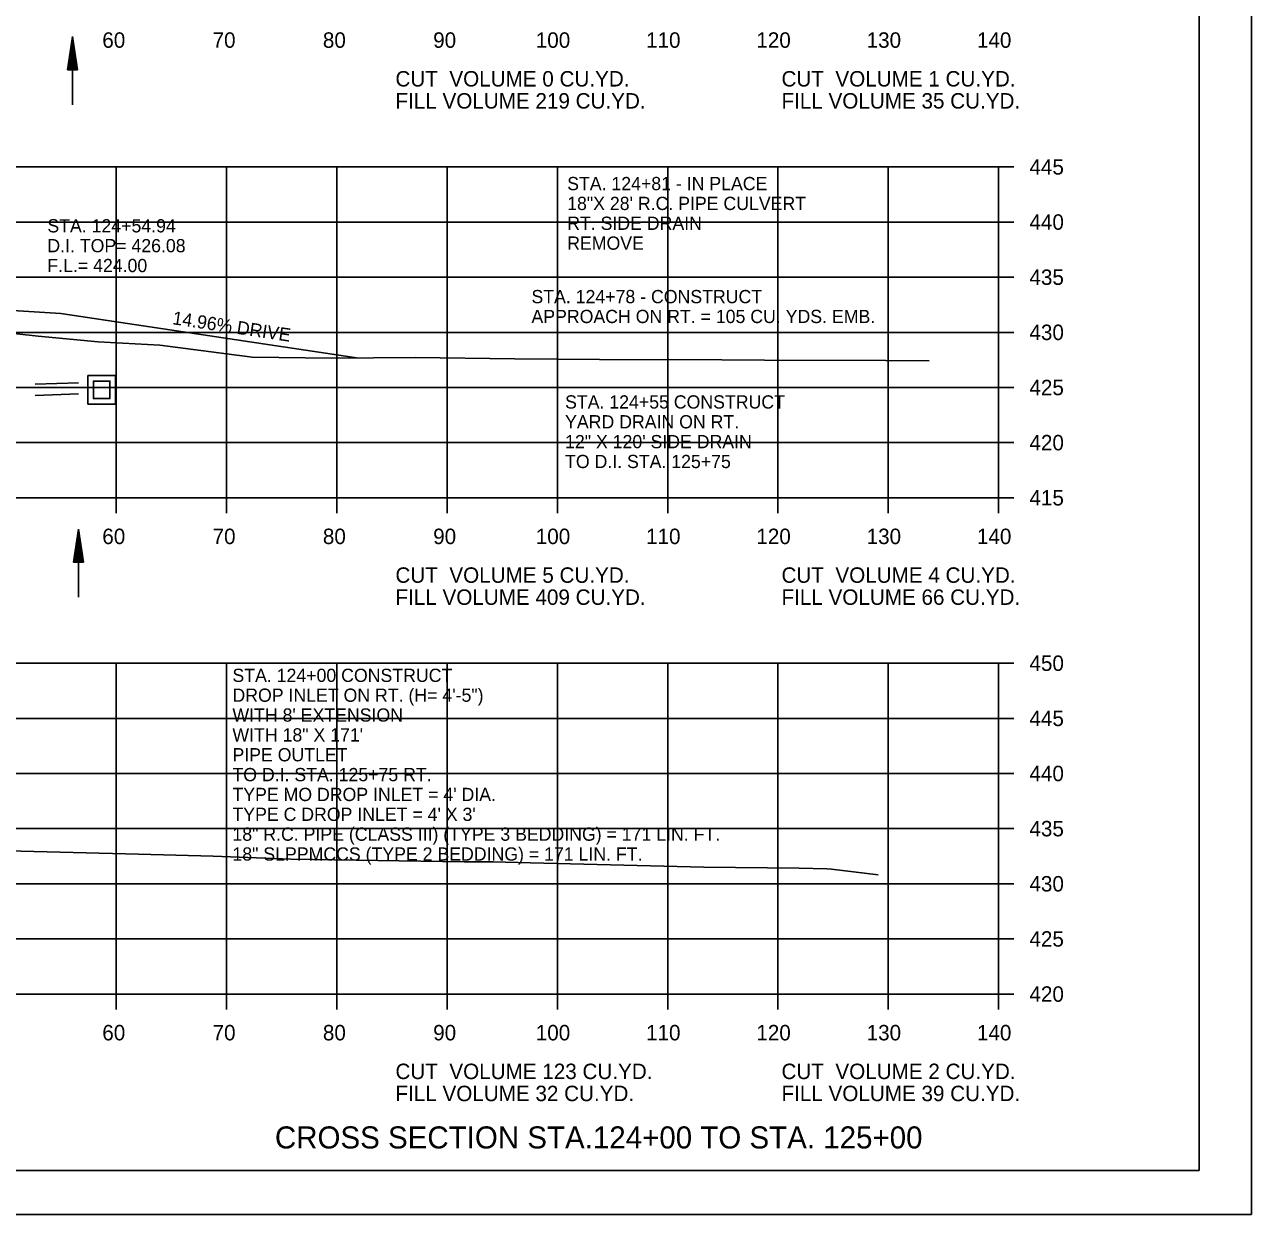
# Model space of a CAD drawing. Extents: x 1538688 to 1540766, y 656250 to 671912.
# Drawn here: x 1538909.9 to 1539021.1, y 659751.3 to 659859.2 of the extents above; entities that cross this region are included whole.
import ezdxf

# ---------------------------------------------------------------- set-up
doc = ezdxf.new("R2010")
doc.units = 0
for name, color, linetype in [('15', 7, 'Continuous'), ('16', 7, 'Continuous'), ('18', 7, 'Continuous'), ('22', 7, 'Continuous'), ('26', 7, 'Continuous'), ('39', 7, 'Continuous'), ('40', 7, 'Continuous'), ('7', 7, 'Continuous'), ('Borings', 7, 'Continuous'), ('Default', 7, 'Continuous'), ('Horizontal Alignment', 7, 'Continuous'), ('RipRap', 7, 'Continuous')]:
    doc.layers.add(name, color=color, linetype=linetype)

msp = doc.modelspace()

# ---------------------------------------------------------------- linework, layer by layer
at = {"layer": '15'}
for p, q in [((1538913.78, 659855.1), (1538914.23, 659858.1)), ((1538914.68, 659855.1), (1538914.23, 659858.1)), ((1538913.86, 659855.1), (1538914.23, 659857.6)), ((1538913.94, 659855.1), (1538914.23, 659857.09)), ((1538914.61, 659855.1), (1538914.23, 659857.6)), ((1538914.53, 659855.1), (1538914.23, 659857.09)), ((1538914.01, 659855.1), (1538914.23, 659856.59)), ((1538914.09, 659855.1), (1538914.23, 659856.08)), ((1538914.46, 659855.1), (1538914.23, 659856.59)), ((1538914.38, 659855.1), (1538914.23, 659856.08)), ((1538913.78, 659855.1), (1538914.68, 659855.1)), ((1538914.16, 659855.1), (1538914.23, 659855.58)), ((1538914.3, 659855.1), (1538914.23, 659855.58)), ((1538914.32, 659810.45), (1538914.77, 659813.45)), ((1538914.39, 659810.45), (1538914.77, 659812.95)), ((1538914.47, 659810.45), (1538914.77, 659812.44)), ((1538915.22, 659810.45), (1538914.77, 659813.45)), ((1538915.14, 659810.45), (1538914.77, 659812.95)), ((1538915.07, 659810.45), (1538914.77, 659812.44)), ((1538914.54, 659810.45), (1538914.77, 659811.94)), ((1538914.62, 659810.45), (1538914.77, 659811.43)), ((1538914.99, 659810.45), (1538914.77, 659811.94)), ((1538914.92, 659810.45), (1538914.77, 659811.43)), ((1538914.32, 659810.45), (1538915.22, 659810.45)), ((1538914.7, 659810.45), (1538914.77, 659810.93)), ((1538914.84, 659810.45), (1538914.77, 659810.93))]:
    msp.add_line(p, q, dxfattribs=at)
at = {"layer": '16'}
for p, q in [((1538913.16, 659833.01), (1538903.17, 659833.6)), ((1538940.18, 659828.96), (1538913.16, 659833.01))]:
    msp.add_line(p, q, dxfattribs=at)
at = {"layer": '18'}
for points in [[(1538897.8, 659832.4), (1538911.1, 659830.95), (1538916.56, 659830.42), (1538922.14, 659830.13), (1538930.52, 659829.04), (1538937.72, 659828.95), (1538945.3, 659829), (1538954.31, 659828.89), (1538958.18, 659828.87), (1538962.01, 659828.84), (1538973.08, 659828.8), (1538976.97, 659828.78), (1538987.95, 659828.74), (1538991.9, 659828.72)], [(1538908.35, 659784.29), (1538920.2, 659783.96), (1538926.98, 659783.8), (1538934.03, 659783.53), (1538949.74, 659783.29), (1538952.36, 659783.27), (1538955.73, 659783.2), (1538971.47, 659782.8), (1538980.1, 659782.69), (1538982.6, 659782.65), (1538983.03, 659782.6), (1538987.28, 659782.1)]]:
    msp.add_lwpolyline(points, dxfattribs=at)
at = {"layer": '22'}
for p, q in [((1538718.18, 659846.29), (1538998.18, 659846.29)), ((1538918.18, 659816.29), (1538918.18, 659846.29)), ((1538928.18, 659816.29), (1538928.18, 659846.29)), ((1538938.18, 659816.29), (1538938.18, 659846.29)), ((1538948.18, 659816.29), (1538948.18, 659846.29)), ((1538958.18, 659816.29), (1538958.18, 659846.29)), ((1538968.18, 659816.29), (1538968.18, 659846.29)), ((1538978.18, 659816.29), (1538978.18, 659846.29)), ((1538988.18, 659816.29), (1538988.18, 659846.29)), ((1538998.18, 659816.29), (1538998.18, 659846.29)), ((1538718.18, 659841.29), (1538998.18, 659841.29)), ((1538718.18, 659836.29), (1538998.18, 659836.29)), ((1538718.18, 659831.29), (1538998.18, 659831.29)), ((1538718.18, 659826.29), (1538998.18, 659826.29)), ((1538718.18, 659821.29), (1538998.18, 659821.29)), ((1538718.18, 659816.29), (1538998.18, 659816.29)), ((1538718.18, 659801.29), (1538998.18, 659801.29)), ((1538918.18, 659771.29), (1538918.18, 659801.29)), ((1538928.18, 659771.29), (1538928.18, 659801.29)), ((1538938.18, 659771.29), (1538938.18, 659801.29)), ((1538948.18, 659771.29), (1538948.18, 659801.29)), ((1538958.18, 659771.29), (1538958.18, 659801.29)), ((1538968.18, 659771.29), (1538968.18, 659801.29)), ((1538978.18, 659771.29), (1538978.18, 659801.29)), ((1538988.18, 659771.29), (1538988.18, 659801.29)), ((1538998.18, 659771.29), (1538998.18, 659801.29)), ((1538718.18, 659796.29), (1538998.18, 659796.29)), ((1538718.18, 659791.29), (1538998.18, 659791.29)), ((1538718.18, 659786.29), (1538998.18, 659786.29)), ((1538718.18, 659781.29), (1538998.18, 659781.29)), ((1538718.18, 659776.29), (1538998.18, 659776.29)), ((1538718.18, 659771.29), (1538998.18, 659771.29))]:
    msp.add_line(p, q, dxfattribs=at)
at = {"layer": '26'}
for p, q in [((1538914.76, 659826.72), (1538910.82, 659826.58)), ((1538914.76, 659825.71), (1538910.82, 659825.57)), ((1538687.78, 659751.31), (1539021.11, 659751.31))]:
    msp.add_line(p, q, dxfattribs=at)
msp.add_lwpolyline([(1538687.77, 659964.64), (1539021.11, 659964.64), (1539021.11, 659751.31), (1538687.77, 659751.31)], close=True, dxfattribs=at)
at = {"layer": '39'}
for p, q in [((1538914.23, 659851.92), (1538914.23, 659858.1)), ((1538914.77, 659807.27), (1538914.77, 659813.45))]:
    msp.add_line(p, q, dxfattribs=at)
for points in [[(1538916.86, 659827.37), (1538918.11, 659827.37), (1538918.11, 659824.79), (1538916.86, 659824.79), (1538915.61, 659824.79), (1538915.61, 659827.37)], [(1538916.86, 659826.87), (1538917.61, 659826.87), (1538917.61, 659825.29), (1538916.86, 659825.29), (1538916.11, 659825.29), (1538916.11, 659826.87)]]:
    msp.add_lwpolyline(points, close=True, dxfattribs=at)
at = {"layer": 'Borings'}
for p, q in [((1538998.18, 659816.29), (1538998.18, 659846.29)), ((1538999.58, 659846.29), (1538998.18, 659846.29)), ((1538999.58, 659841.29), (1538998.18, 659841.29)), ((1538999.58, 659836.29), (1538998.18, 659836.29)), ((1538999.58, 659831.29), (1538998.18, 659831.29)), ((1538999.58, 659826.29), (1538998.18, 659826.29)), ((1538999.58, 659821.29), (1538998.18, 659821.29)), ((1538718.18, 659816.29), (1538998.18, 659816.29)), ((1538918.18, 659814.89), (1538918.18, 659816.29)), ((1538928.18, 659814.89), (1538928.18, 659816.29)), ((1538938.18, 659814.89), (1538938.18, 659816.29)), ((1538948.18, 659814.89), (1538948.18, 659816.29)), ((1538958.18, 659814.89), (1538958.18, 659816.29)), ((1538968.18, 659814.89), (1538968.18, 659816.29)), ((1538978.18, 659814.89), (1538978.18, 659816.29)), ((1538988.18, 659814.89), (1538988.18, 659816.29)), ((1538998.18, 659814.89), (1538998.18, 659816.29)), ((1538999.58, 659816.29), (1538998.18, 659816.29)), ((1538998.18, 659771.29), (1538998.18, 659801.29)), ((1538999.58, 659801.29), (1538998.18, 659801.29)), ((1538999.58, 659796.29), (1538998.18, 659796.29)), ((1538999.58, 659791.29), (1538998.18, 659791.29)), ((1538999.58, 659786.29), (1538998.18, 659786.29)), ((1538999.58, 659781.29), (1538998.18, 659781.29)), ((1538999.58, 659776.29), (1538998.18, 659776.29)), ((1538718.18, 659771.29), (1538998.18, 659771.29)), ((1538918.18, 659769.89), (1538918.18, 659771.29)), ((1538928.18, 659769.89), (1538928.18, 659771.29)), ((1538938.18, 659769.89), (1538938.18, 659771.29)), ((1538948.18, 659769.89), (1538948.18, 659771.29)), ((1538958.18, 659769.89), (1538958.18, 659771.29)), ((1538968.18, 659769.89), (1538968.18, 659771.29)), ((1538978.18, 659769.89), (1538978.18, 659771.29)), ((1538988.18, 659769.89), (1538988.18, 659771.29)), ((1538998.18, 659769.89), (1538998.18, 659771.29)), ((1538999.58, 659771.29), (1538998.18, 659771.29))]:
    msp.add_line(p, q, dxfattribs=at)
at = {"layer": 'RipRap'}
for q in [(1539016.36, 659960.75), (1538700.18, 659755.29)]:
    msp.add_line((1539016.36, 659755.29), q, dxfattribs=at)

# ---------------------------------------------------------------- texts
at = {"layer": '15'}
msp.add_text('CROSS SECTION STA.124+00 TO STA. 125+00', height=2, dxfattribs=at).set_placement((1538932.57, 659757.29))
at = {"layer": '16'}
msp.add_text('14.96% DRIVE', height=1.2, rotation=351.4914, dxfattribs=at).set_placement((1538923.23, 659832.03))
at = {"layer": '40'}
for s, p in [('STA. 124+54.94', (1538911.94, 659840.35)), ('D.I. TOP= 426.08', (1538911.94, 659838.55)), ('F.L.= 424.00', (1538911.94, 659836.75)), ('STA. 124+55 CONSTRUCT', (1538958.88, 659824.38)), ('YARD DRAIN ON RT. ', (1538958.88, 659822.58)), ('12" X 120\' SIDE DRAIN', (1538958.88, 659820.78)), ('TO D.I. STA. 125+75', (1538958.88, 659818.98)), ('STA. 124+00 CONSTRUCT', (1538928.72, 659799.59)), ('DROP INLET ON RT. (H= 4\'-5") ', (1538928.72, 659797.79)), ("WITH 8' EXTENSION ", (1538928.72, 659795.99)), ('WITH 18" X 171\'', (1538928.72, 659794.19)), ('PIPE OUTLET', (1538928.72, 659792.39)), ('TO D.I. STA. 125+75 RT.', (1538928.72, 659790.59)), ("TYPE MO DROP INLET = 4' DIA.", (1538928.72, 659788.79)), ("TYPE C DROP INLET = 4' X 3'", (1538928.72, 659786.99)), ('18" R.C. PIPE (CLASS III) (TYPE 3 BEDDING) = 171 LIN. FT.', (1538928.72, 659785.19)), ('18" SLPPMCCS (TYPE 2 BEDDING) = 171 LIN. FT.', (1538928.72, 659783.39))]:
    msp.add_text(s, height=1.2, dxfattribs=at).set_placement(p)
at = {"layer": '7'}
for s, p in [('STA. 124+78 - CONSTRUCT', (1538955.83, 659833.93)), ('APPROACH ON RT. = 105 CU. YDS. EMB.', (1538955.83, 659832.13))]:
    msp.add_text(s, height=1.2, dxfattribs=at).set_placement(p)
at = {"layer": 'Default'}
for s, p in [('STA. 124+81 - IN PLACE', (1538959.07, 659844.18)), ('18"X 28\' R.C. PIPE CULVERT', (1538959.07, 659842.38)), ('RT. SIDE DRAIN', (1538959.07, 659840.58)), ('REMOVE', (1538959.07, 659838.78))]:
    msp.add_text(s, height=1.2, dxfattribs=at).set_placement(p)
at = {"layer": 'Horizontal Alignment'}
for s, p in [('60', (1538916.92, 659857.09)), ('70', (1538926.92, 659857.09)), ('80', (1538936.92, 659857.09)), ('90', (1538946.92, 659857.09)), ('100', (1538956.22, 659857.09)), ('110', (1538966.22, 659857.09)), ('120', (1538976.22, 659857.09)), ('130', (1538986.22, 659857.09)), ('140', (1538996.22, 659857.09)), ('CUT  VOLUME 0 CU.YD.', (1538943.5, 659853.58)), ('CUT  VOLUME 1 CU.YD.', (1538978.5, 659853.58)), ('FILL VOLUME 219 CU.YD.', (1538943.5, 659851.58)), ('FILL VOLUME 35 CU.YD.', (1538978.5, 659851.58)), ('445', (1539000.98, 659845.59)), ('440', (1539000.98, 659840.59)), ('435', (1539000.98, 659835.59)), ('430', (1539000.98, 659830.59)), ('425', (1539000.98, 659825.59)), ('420', (1539000.98, 659820.59)), ('415', (1539000.98, 659815.59)), ('60', (1538916.92, 659812.09)), ('70', (1538926.92, 659812.09)), ('80', (1538936.92, 659812.09)), ('90', (1538946.92, 659812.09)), ('100', (1538956.22, 659812.09)), ('110', (1538966.22, 659812.09)), ('120', (1538976.22, 659812.09)), ('130', (1538986.22, 659812.09)), ('140', (1538996.22, 659812.09)), ('CUT  VOLUME 5 CU.YD.', (1538943.5, 659808.58)), ('CUT  VOLUME 4 CU.YD.', (1538978.5, 659808.58)), ('FILL VOLUME 409 CU.YD.', (1538943.5, 659806.58)), ('FILL VOLUME 66 CU.YD.', (1538978.5, 659806.58)), ('450', (1539000.98, 659800.59)), ('445', (1539000.98, 659795.59)), ('440', (1539000.98, 659790.59)), ('435', (1539000.98, 659785.59)), ('430', (1539000.98, 659780.59)), ('425', (1539000.98, 659775.59)), ('420', (1539000.98, 659770.59)), ('60', (1538916.92, 659767.09)), ('70', (1538926.92, 659767.09)), ('80', (1538936.92, 659767.09)), ('90', (1538946.92, 659767.09)), ('100', (1538956.22, 659767.09)), ('110', (1538966.22, 659767.09)), ('120', (1538976.22, 659767.09)), ('130', (1538986.22, 659767.09)), ('140', (1538996.22, 659767.09)), ('CUT  VOLUME 123 CU.YD.', (1538943.5, 659763.58)), ('CUT  VOLUME 2 CU.YD.', (1538978.5, 659763.58)), ('FILL VOLUME 32 CU.YD.', (1538943.5, 659761.58)), ('FILL VOLUME 39 CU.YD.', (1538978.5, 659761.58))]:
    msp.add_text(s, height=1.4, dxfattribs=at).set_placement(p)

doc.saveas('drawing.dxf')
